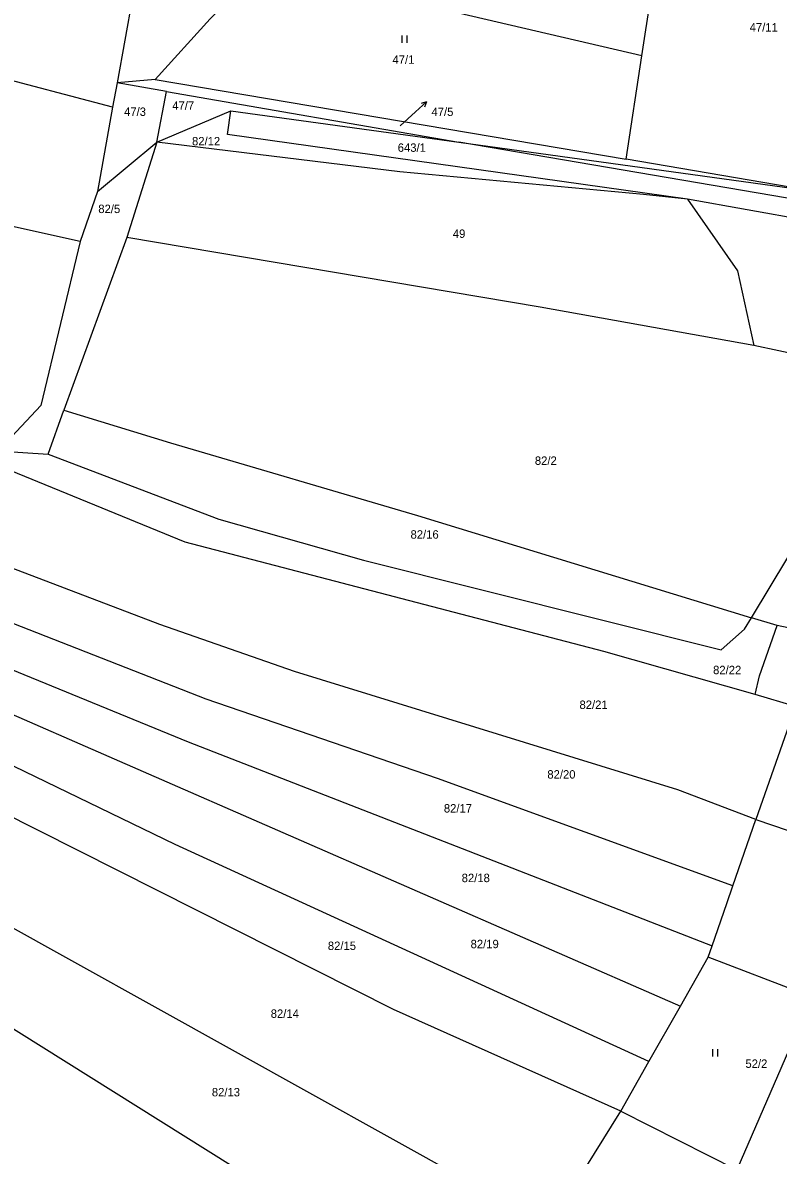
# Model space of a CAD drawing. Extents: x -746176 to -739709, y -1128407 to -1124482.
# Drawn here: x -743188.7 to -743036.1, y -1127574.6 to -1127345.9 of the extents above; entities that cross this region are included whole.
import ezdxf

# ---------------------------------------------------------------- set-up
doc = ezdxf.new("R2010")
doc.units = 0
for name, color, linetype in [('Hranice parcel', 7, 'Continuous'), ('Parcelní čísla', 7, 'Continuous'), ('Pop  PČ popisy', 7, 'Continuous'), ('Značky kultur', 7, 'Continuous')]:
    doc.layers.add(name, color=color, linetype=linetype)

msp = doc.modelspace()

# ---------------------------------------------------------------- linework, layer by layer
at = {"layer": 'Hranice parcel'}
for p, q in [((-743163.52, -1127323.93), (-743169.65, -1127358.07)), ((-743063.68, -1127352.59), (-743059.46, -1127325.17)), ((-743063.68, -1127352.59), (-743140.7, -1127334.62)), ((-743066.9, -1127373.47), (-743063.68, -1127352.59)), ((-743169.65, -1127358.07), (-743170.53, -1127362.98)), ((-743161.95, -1127357.36), (-743169.65, -1127358.07)), ((-743159.66, -1127359.81), (-743169.65, -1127358.07)), ((-743161.95, -1127357.36), (-743066.9, -1127373.47)), ((-743161.61, -1127370.05), (-743159.66, -1127359.81)), ((-743159.66, -1127359.81), (-743100.68, -1127370.05)), ((-743170.53, -1127362.98), (-743173.59, -1127379.99)), ((-743161.61, -1127370.05), (-743146.67, -1127363.71)), ((-743146.67, -1127363.71), (-743100.68, -1127370.05)), ((-743173.59, -1127379.99), (-743161.61, -1127370.05)), ((-743161.61, -1127370.05), (-743167.67, -1127389.27)), ((-743100.68, -1127370.05), (-743028.55, -1127379.99)), ((-743028.55, -1127379.99), (-743066.9, -1127373.47)), ((-743173.59, -1127379.99), (-743177.11, -1127390.05)), ((-743177.11, -1127390.05), (-743199.65, -1127385.13)), ((-743167.67, -1127389.27), (-743180.36, -1127424.17)), ((-743009.13, -1127417.82), (-743041.1, -1127411.11)), ((-743183.58, -1127433.05), (-743180.36, -1127424.17)), ((-743202.45, -1127431.75), (-743183.58, -1127433.05)), ((-743036.38, -1127467.62), (-743041.59, -1127466.09)), ((-743027.39, -1127469.59), (-743036.38, -1127467.62)), ((-743032.69, -1127483.96), (-743040.81, -1127481.55)), ((-743032.69, -1127483.96), (-743040.66, -1127506.77)), ((-743082.43, -1127588.87), (-743239.89, -1127501.37)), ((-743045.31, -1127520.19), (-743040.66, -1127506.77)), ((-743040.66, -1127506.77), (-743018.83, -1127514.29)), ((-743050.32, -1127534.62), (-743049.5, -1127532.27)), ((-743055.93, -1127544.5), (-743050.32, -1127534.62)), ((-743029.41, -1127542.64), (-743050.32, -1127534.62)), ((-743029.41, -1127542.64), (-743044.5, -1127577.53)), ((-743062.27, -1127555.66), (-743055.93, -1127544.5)), ((-743067.95, -1127565.66), (-743062.27, -1127555.66)), ((-743082.43, -1127588.87), (-743067.95, -1127565.66)), ((-743067.95, -1127565.66), (-743044.5, -1127577.53))]:
    msp.add_line(p, q, dxfattribs=at)
for points in [[(-743170.53, -1127362.98), (-743196.16, -1127356.25), (-743296.23, -1127335.74)], [(-743140.7, -1127334.62), (-743150.85, -1127345.11), (-743161.95, -1127357.36)], [(-743054.48, -1127381.54), (-743147.34, -1127368.46), (-743146.67, -1127363.71)], [(-743054.48, -1127381.54), (-743063.36, -1127380.56), (-743112.56, -1127376.02), (-743161.61, -1127370.05)], [(-742967.2, -1127394.53), (-742996.94, -1127389.89), (-743028.35, -1127382.31), (-743100.68, -1127370.05)], [(-743021.3, -1127386.55), (-743030.41, -1127385.86), (-743054.48, -1127381.54)], [(-743054.48, -1127381.54), (-743044.4, -1127395.97), (-743041.1, -1127411.11)], [(-743177.11, -1127390.05), (-743185.02, -1127423.21), (-743191.91, -1127430.5), (-743207.37, -1127426.59)], [(-743041.1, -1127411.11), (-743084.2, -1127403.32), (-743167.67, -1127389.27)], [(-743180.36, -1127424.17), (-743158.88, -1127430.74), (-743108.99, -1127445.38), (-743041.59, -1127466.09)], [(-743040.81, -1127481.55), (-743071.4, -1127472.85), (-743155.92, -1127450.8), (-743202.45, -1127431.75)], [(-743183.58, -1127433.05), (-743149.11, -1127446.12), (-743119.92, -1127454.41), (-743047.66, -1127472.53), (-743042.97, -1127468.39), (-743041.59, -1127466.09)], [(-743041.59, -1127466.09), (-743027.12, -1127442.06), (-743016.5, -1127438.72)], [(-743040.66, -1127506.77), (-743056.44, -1127500.82), (-743133.85, -1127476.88), (-743160.99, -1127467.42), (-743199.57, -1127452.71), (-743214.09, -1127445.46)], [(-743045.31, -1127520.19), (-743104.96, -1127498.48), (-743151.66, -1127482.51), (-743195.56, -1127465.33), (-743218.68, -1127453.92)], [(-743221.96, -1127460.98), (-743195.25, -1127474.76), (-743155.28, -1127491.09), (-743049.5, -1127532.27)], [(-743225.6, -1127468.62), (-743200.19, -1127481.49), (-743164.36, -1127497.11), (-743055.93, -1127544.5)], [(-743040.81, -1127481.55), (-743039.98, -1127477.77), (-743036.38, -1127467.62)], [(-743062.27, -1127555.66), (-743157.93, -1127511.82), (-743229.49, -1127477.19)], [(-743067.95, -1127565.66), (-743113.85, -1127545.15), (-743233.06, -1127485.07)], [(-743096.19, -1127609.82), (-743127.6, -1127588.59), (-743246.36, -1127514.17)], [(-743049.5, -1127532.27), (-743046.55, -1127523.76), (-743045.31, -1127520.19)]]:
    msp.add_lwpolyline(points, dxfattribs=at)
at = {"layer": 'Pop  PČ popisy'}
for p, q in [((-743109.4, -1127363.92), (-743107.17, -1127361.91)), ((-743107.17, -1127361.91), (-743108.25, -1127362.21)), ((-743107.17, -1127361.91), (-743107.58, -1127362.95)), ((-743112.48, -1127366.7), (-743109.4, -1127363.92))]:
    msp.add_line(p, q, dxfattribs=at)
at = {"layer": 'Značky kultur'}
for p, q in [((-743112.08, -1127349.98), (-743112.08, -1127348.48)), ((-743111.08, -1127349.98), (-743111.08, -1127348.48)), ((-743049.37, -1127554.65), (-743049.37, -1127553.15)), ((-743048.37, -1127554.65), (-743048.37, -1127553.15))]:
    msp.add_line(p, q, dxfattribs=at)

# ---------------------------------------------------------------- texts
at = {"layer": 'Parcelní čísla'}
for s, p in [('47/11', (-743041.94, -1127347.69)), ('47/1', (-743114.04, -1127354.19)), ('47/3', (-743168.23, -1127364.72)), ('47/7', (-743158.5, -1127363.48)), ('47/5', (-743106.17, -1127364.74)), ('82/12', (-743154.51, -1127370.67)), ('643/1', (-743112.98, -1127371.97)), ('82/5', (-743173.43, -1127384.34)), ('49', (-743101.86, -1127389.35)), ('82/2', (-743085.3, -1127435.18)), ('82/16', (-743110.4, -1127450.08)), ('82/22', (-743049.32, -1127477.45)), ('82/21', (-743076.29, -1127484.47)), ('82/20', (-743082.78, -1127498.53)), ('82/17', (-743103.67, -1127505.38)), ('82/18', (-743100.07, -1127519.44)), ('82/15', (-743127.09, -1127533.14)), ('82/19', (-743098.27, -1127532.78)), ('82/14', (-743138.62, -1127546.84)), ('52/2', (-743042.79, -1127556.94)), ('82/13', (-743150.51, -1127562.7))]:
    msp.add_text(s, height=1.7, dxfattribs=at).set_placement(p)

doc.saveas('drawing.dxf')
